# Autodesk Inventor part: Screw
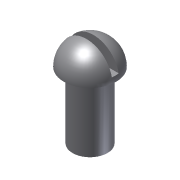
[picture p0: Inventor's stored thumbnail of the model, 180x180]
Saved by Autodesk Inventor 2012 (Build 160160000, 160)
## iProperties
Created: 2009-04
Part Number: Screw
Document SubType Name: Modeling
Designer: Sham
Density: 1 g/cm^3
Material: Default
Mass: 17.9575 g
Surface Area: 49.7899 cm^2
Volume: 17.9575 cm^3
Author: Sham
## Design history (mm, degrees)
sketch "Sketch1"
  geometry: C1 r 10 at (0, 0)
  constraints: 1 centre point
  dimensions: "d0" = 20 diameter of C1
extrude "Extrusion1" new body sketch "Sketch1" distance "d1" = 38; taper "d2" = 0 deg
sketch "Sketch2"
  geometry: L1 (0, 38)-(-15, 38); L2 (-10, 38)-(10, 38) reference; L3 (0, 38)-(0, 53); A1 r 15 centre (0, 38) between (0, 53) and (-15, 38)
  constraints: 4 end point, 2 point on circle, 1 centre point, 1 collinear, 1 perpendicular
  dimensions: "d3" = 15 radius of A1
revolve "Revolution1" sketch "Sketch2" stored, may be unused: angle "d4" = 90 deg
sketch "Sketch3"
  geometry: L1 (2, 54)-(2, 41); L2 (2, 41)-(-2, 41); L3 (-2, 41)-(-2, 54); L4 (-2, 54)-(2, 54); L5 (15, 38)-(-15, 38) reference
  constraints: 8 end point, 2 parallel, 1 perpendicular, 1 vertical
  dimensions: "d5" = 3 distance between parallel lines of L5 L2; "d6" = 4 distance between parallel lines of L3 L1
extrude "Extrusion2" cut sketch "Sketch3" stored distance "d7" = 38; taper "d8" = 0 deg
body "Solid1"
